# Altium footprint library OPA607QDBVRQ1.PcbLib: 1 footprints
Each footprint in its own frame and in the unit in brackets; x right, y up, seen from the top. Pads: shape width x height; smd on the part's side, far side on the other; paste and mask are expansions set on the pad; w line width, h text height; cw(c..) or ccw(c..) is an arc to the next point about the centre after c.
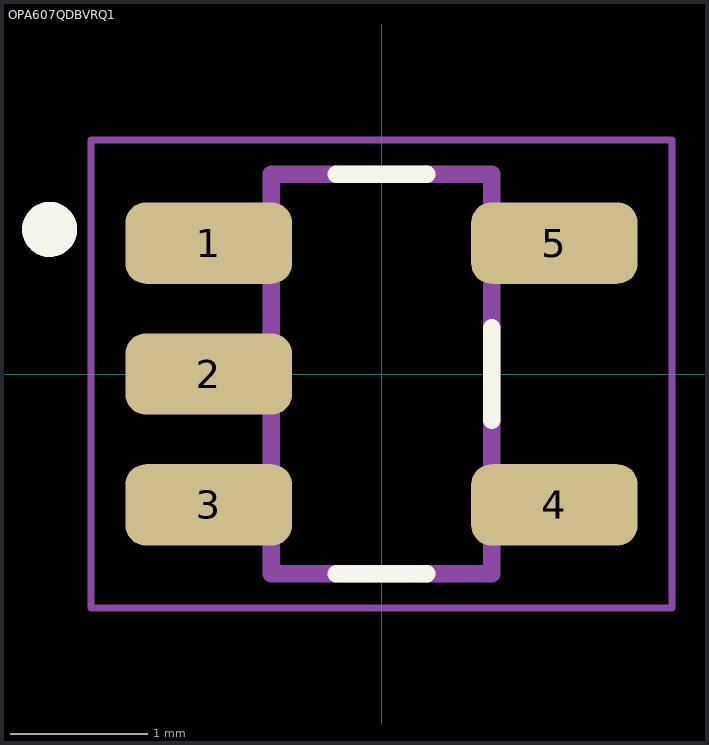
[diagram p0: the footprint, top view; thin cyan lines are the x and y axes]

## OPA607QDBVRQ1 [mm]
pads (5):
  rrect50% 1.21x0.59 smd: 1(-1.255,0.95) 2(-1.255,0) 3(-1.255,-0.95) 4(1.255,-0.95) 5(1.255,0.95)
Top Overlay:
  circle w0.2: c-2.41,1.05 r0.1
  lines w0.127: -0.33,-1.45 0.33,-1.45 ; -0.33,1.45 0.33,1.45 ; 0.8,-0.335 0.8,0.335
Mechanical 13:
  circle w0.2: c-2.41,1.05 r0.1
  lines w0.127: -0.8,-1.45 -0.8,1.45 0.8,1.45 0.8,-1.45 -0.8,-1.45
Mechanical 15:
  lines w0.05: -2.11,-1.7 2.11,-1.7 2.11,1.7 -2.11,1.7 -2.11,-1.7
3D body "OPA607QDBVRQ1.STEP": height 1.45, standoff 0, extent -1.4,-1.45 1.4,1.45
